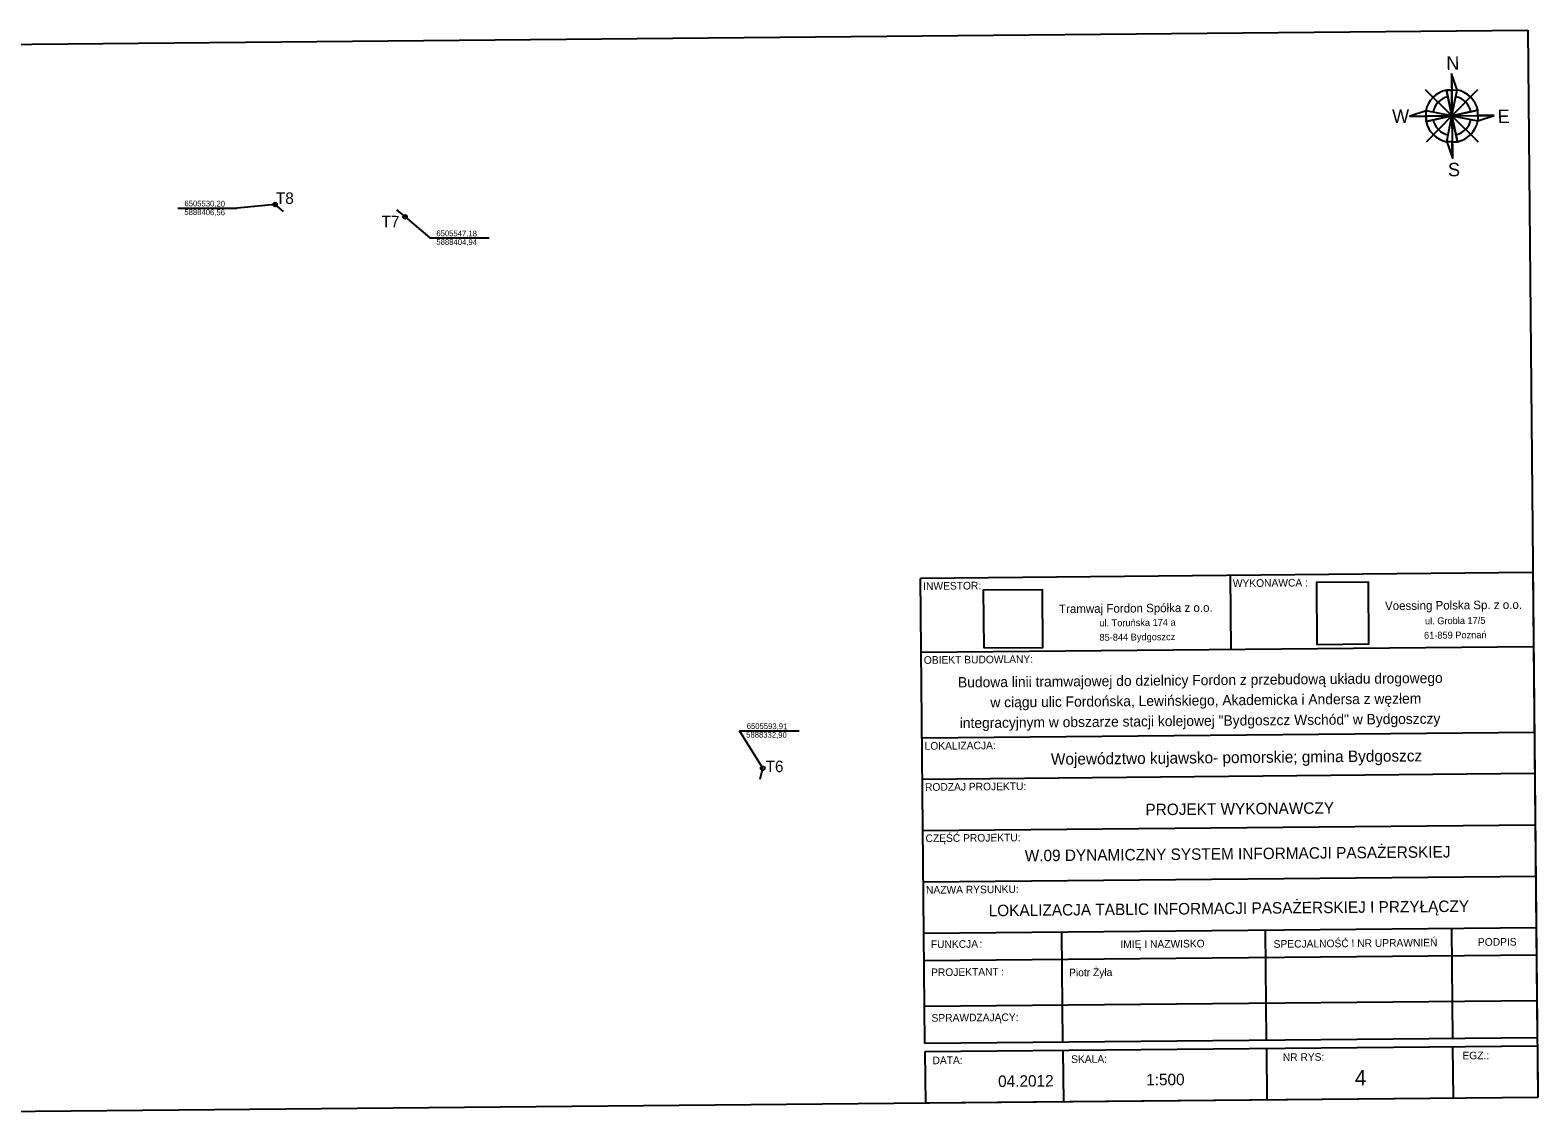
# Model space of a CAD drawing. Extents: x 6505045 to 6511721, y 5887996 to 5893535.
# Drawn here: x 6505498.2 to 6505695.2, y 5888288 to 5888429.3 of the extents above; entities that cross this region are included whole.
import ezdxf

# ---------------------------------------------------------------- set-up
doc = ezdxf.new("R2010")
doc.units = 0
for name, color, linetype in [('__legenda', 7, 'Continuous'), ('Default', 7, 'Continuous'), ('P_2 tablice LCD', 7, 'Continuous'), ('P_lokalizacja slupka', 7, 'Continuous'), ('P_opisy', 7, 'Continuous'), ('P_tabela', 7, 'Continuous'), ('P_wsporzedne', 7, 'Continuous'), ('P_znak północy', 7, 'Continuous'), ('SA_Linie-020', 7, 'Continuous'), ('SA_Stempel_Text-020', 7, 'Continuous'), ('SA_Stempel_Text-030', 7, 'Continuous'), ('SA_Stempel_Text-035', 7, 'Continuous'), ('SA_Unterschrift_Text', 7, 'Continuous')]:
    doc.layers.add(name, color=color, linetype=linetype)

msp = doc.modelspace()

# ---------------------------------------------------------------- linework, layer by layer
at = {"layer": '__legenda'}
msp.add_lwpolyline([(6505666.3, 5888349.09), (6505673.1, 5888349.15), (6505673.03, 5888357.22), (6505666.23, 5888357.16)], close=True, dxfattribs=at)
at = {"layer": 'Default'}
msp.add_lwpolyline([(6505622.78, 5888348.62), (6505630.51, 5888348.69), (6505630.44, 5888356.23), (6505622.71, 5888356.16)], close=True, dxfattribs=at)
at = {"layer": 'P_2 tablice LCD'}
for p, q in [((6505531.32, 5888405.65), (6505530.2, 5888406.56)), ((6505546.05, 5888405.86), (6505547.18, 5888404.94)), ((6505593.58, 5888331.48), (6505593.91, 5888332.9))]:
    msp.add_line(p, q, dxfattribs=at)
at = {"layer": 'P_lokalizacja slupka'}
for centre in [(6505530.2, 5888406.56), (6505547.18, 5888404.94), (6505593.91, 5888332.9)]:
    msp.add_circle(centre, 0.25, dxfattribs=at)
at = {"layer": 'P_tabela'}
for p, q in [((6505492.87, 5888427.46), (6505693.86, 5888429.33)), ((6505492.87, 5888427.46), (6505693.86, 5888429.33)), ((6505492.87, 5888427.46), (6505693.86, 5888429.33)), ((6505693.86, 5888429.33), (6505695.16, 5888289.89)), ((6505693.86, 5888429.33), (6505695.16, 5888289.89)), ((6505693.86, 5888429.33), (6505695.16, 5888289.89)), ((6505695.16, 5888289.89), (6505494.18, 5888288.01)), ((6505695.16, 5888289.89), (6505494.18, 5888288.01)), ((6505695.16, 5888289.89), (6505494.18, 5888288.01))]:
    msp.add_line(p, q, dxfattribs=at)
at = {"layer": 'P_wsporzedne'}
for p, q in [((6505517.5, 5888406.08), (6505525.27, 5888406.08)), ((6505530.2, 5888406.56), (6505525.27, 5888406.08)), ((6505547.18, 5888404.94), (6505550.41, 5888402.18)), ((6505550.41, 5888402.18), (6505558.18, 5888402.18)), ((6505590.88, 5888337.8), (6505598.65, 5888337.8)), ((6505593.91, 5888332.9), (6505590.88, 5888337.8))]:
    msp.add_line(p, q, dxfattribs=at)
at = {"layer": 'P_znak północy'}
for p, q in [((6505683.89, 5888423.66), (6505683.99, 5888412.62)), ((6505683.89, 5888423.66), (6505683.99, 5888412.62)), ((6505683.89, 5888423.66), (6505683.99, 5888412.62)), ((6505683.92, 5888418.14), (6505680.49, 5888421.52)), ((6505683.92, 5888418.14), (6505680.49, 5888421.52)), ((6505683.92, 5888418.14), (6505680.49, 5888421.52)), ((6505683.22, 5888421.51), (6505683.91, 5888421.51)), ((6505683.93, 5888418.14), (6505683.22, 5888421.51)), ((6505683.22, 5888421.51), (6505683.91, 5888421.51)), ((6505683.93, 5888418.14), (6505683.22, 5888421.51)), ((6505683.22, 5888421.51), (6505683.91, 5888421.51)), ((6505683.93, 5888418.14), (6505683.22, 5888421.51)), ((6505683.91, 5888421.51), (6505684.6, 5888421.52)), ((6505683.91, 5888421.51), (6505684.6, 5888421.52)), ((6505683.91, 5888421.51), (6505684.6, 5888421.52)), ((6505683.93, 5888418.14), (6505684.6, 5888421.52)), ((6505683.93, 5888418.14), (6505684.6, 5888421.52)), ((6505683.93, 5888418.14), (6505684.6, 5888421.52)), ((6505683.94, 5888418.15), (6505687.32, 5888421.58)), ((6505683.94, 5888418.15), (6505687.32, 5888421.58)), ((6505683.94, 5888418.15), (6505687.32, 5888421.58)), ((6505678.42, 5888418.08), (6505689.46, 5888418.19)), ((6505678.42, 5888418.08), (6505689.46, 5888418.19)), ((6505678.42, 5888418.08), (6505689.46, 5888418.19)), ((6505683.93, 5888418.14), (6505680.55, 5888418.79)), ((6505683.93, 5888418.14), (6505680.55, 5888418.79)), ((6505683.93, 5888418.14), (6505680.55, 5888418.79)), ((6505683.94, 5888418.15), (6505680.55, 5888414.69)), ((6505683.94, 5888418.15), (6505680.55, 5888414.69)), ((6505683.94, 5888418.15), (6505680.55, 5888414.69)), ((6505680.56, 5888418.1), (6505683.92, 5888418.14)), ((6505680.56, 5888418.1), (6505683.92, 5888418.14)), ((6505680.56, 5888418.1), (6505683.92, 5888418.14)), ((6505680.57, 5888417.41), (6505680.56, 5888418.1)), ((6505680.57, 5888417.41), (6505680.56, 5888418.1)), ((6505680.57, 5888417.41), (6505680.56, 5888418.1)), ((6505680.57, 5888417.41), (6505683.93, 5888418.14)), ((6505683.92, 5888418.14), (6505680.57, 5888417.41)), ((6505680.57, 5888417.41), (6505683.93, 5888418.14)), ((6505683.92, 5888418.14), (6505680.57, 5888417.41)), ((6505680.57, 5888417.41), (6505683.93, 5888418.14)), ((6505683.92, 5888418.14), (6505680.57, 5888417.41)), ((6505683.28, 5888414.75), (6505683.93, 5888418.14)), ((6505683.28, 5888414.75), (6505683.93, 5888418.14)), ((6505683.28, 5888414.75), (6505683.93, 5888418.14)), ((6505683.93, 5888418.14), (6505687.31, 5888418.86)), ((6505683.93, 5888418.14), (6505687.31, 5888418.86)), ((6505683.93, 5888418.14), (6505687.31, 5888418.86)), ((6505683.93, 5888418.14), (6505687.32, 5888417.48)), ((6505683.93, 5888418.14), (6505684.66, 5888414.76)), ((6505683.93, 5888418.14), (6505687.32, 5888417.48)), ((6505683.93, 5888418.14), (6505684.66, 5888414.76)), ((6505683.93, 5888418.14), (6505687.32, 5888417.48)), ((6505683.93, 5888418.14), (6505684.66, 5888414.76)), ((6505683.94, 5888418.15), (6505687.38, 5888414.75)), ((6505683.94, 5888418.15), (6505687.38, 5888414.75)), ((6505683.94, 5888418.15), (6505687.38, 5888414.75))]:
    msp.add_line(p, q, dxfattribs=at)
for points in [[(6505683.89, 5888423.66), (6505683.91, 5888421.51), (6505683.91, 5888421.51), (6505684.6, 5888421.52), (6505683.89, 5888423.66)], [(6505683.89, 5888423.66), (6505683.91, 5888421.51), (6505683.91, 5888421.51), (6505684.6, 5888421.52), (6505683.89, 5888423.66)], [(6505683.89, 5888423.66), (6505683.91, 5888421.51), (6505683.91, 5888421.51), (6505684.6, 5888421.52), (6505683.89, 5888423.66)], [(6505683.94, 5888418.15), (6505683.91, 5888421.51), (6505683.22, 5888421.51), (6505683.93, 5888418.14), (6505683.94, 5888418.15)], [(6505683.94, 5888418.15), (6505683.91, 5888421.51), (6505683.22, 5888421.51), (6505683.93, 5888418.14), (6505683.94, 5888418.15)], [(6505683.94, 5888418.15), (6505683.91, 5888421.51), (6505683.22, 5888421.51), (6505683.93, 5888418.14), (6505683.94, 5888418.15)], [(6505680.56, 5888418.1), (6505680.55, 5888418.79), (6505678.42, 5888418.08), (6505680.56, 5888418.1)], [(6505680.56, 5888418.1), (6505680.55, 5888418.79), (6505678.42, 5888418.08), (6505680.56, 5888418.1)], [(6505680.56, 5888418.1), (6505680.55, 5888418.79), (6505678.42, 5888418.08), (6505680.56, 5888418.1)], [(6505683.92, 5888418.14), (6505680.56, 5888418.1), (6505680.57, 5888417.41), (6505683.92, 5888418.14)], [(6505683.92, 5888418.14), (6505680.56, 5888418.1), (6505680.57, 5888417.41), (6505683.92, 5888418.14)], [(6505683.92, 5888418.14), (6505680.56, 5888418.1), (6505680.57, 5888417.41), (6505683.92, 5888418.14)], [(6505683.94, 5888418.14), (6505683.94, 5888418.14), (6505683.95, 5888418.14), (6505687.32, 5888418.17), (6505687.31, 5888418.86), (6505683.94, 5888418.14)], [(6505683.94, 5888418.14), (6505683.94, 5888418.14), (6505683.95, 5888418.14), (6505687.32, 5888418.17), (6505687.31, 5888418.86), (6505683.94, 5888418.14)], [(6505683.94, 5888418.14), (6505683.94, 5888418.14), (6505683.95, 5888418.14), (6505687.32, 5888418.17), (6505687.31, 5888418.86), (6505683.94, 5888418.14)], [(6505683.97, 5888414.76), (6505684.66, 5888414.76), (6505683.94, 5888418.13), (6505683.97, 5888414.76)], [(6505683.97, 5888414.76), (6505684.66, 5888414.76), (6505683.94, 5888418.13), (6505683.97, 5888414.76)], [(6505683.97, 5888414.76), (6505684.66, 5888414.76), (6505683.94, 5888418.13), (6505683.97, 5888414.76)], [(6505689.46, 5888418.19), (6505687.32, 5888418.17), (6505687.32, 5888417.48), (6505689.46, 5888418.19)], [(6505689.46, 5888418.19), (6505687.32, 5888418.17), (6505687.32, 5888417.48), (6505689.46, 5888418.19)], [(6505689.46, 5888418.19), (6505687.32, 5888418.17), (6505687.32, 5888417.48), (6505689.46, 5888418.19)], [(6505683.97, 5888414.76), (6505683.28, 5888414.75), (6505683.99, 5888412.62), (6505683.97, 5888414.76)], [(6505683.97, 5888414.76), (6505683.28, 5888414.75), (6505683.99, 5888412.62), (6505683.97, 5888414.76)], [(6505683.97, 5888414.76), (6505683.28, 5888414.75), (6505683.99, 5888412.62), (6505683.97, 5888414.76)]]:
    msp.add_lwpolyline(points, dxfattribs=at)
for centre, radius, start, end in [((6505683.93, 5888418.14), 3.45, 102.0474, 168.9738), ((6505683.93, 5888418.14), 3.45, 102.0474, 168.9738), ((6505683.93, 5888418.14), 3.45, 102.0474, 168.9738), ((6505683.94, 5888418.15), 2.53, 102.1671, 169.2958), ((6505683.94, 5888418.15), 2.53, 102.1671, 169.2958), ((6505683.94, 5888418.15), 2.53, 102.1671, 169.2958), ((6505683.94, 5888418.15), 2.53, 11.7816, 78.9353), ((6505683.94, 5888418.15), 2.53, 11.7816, 78.9353), ((6505683.94, 5888418.15), 2.53, 11.7816, 78.9353), ((6505683.94, 5888418.14), 3.45, 12.0554, 79.0163), ((6505683.94, 5888418.14), 3.45, 12.0554, 79.0163), ((6505683.94, 5888418.14), 3.45, 12.0554, 79.0163), ((6505683.93, 5888418.13), 3.45, 192.0538, 259.0158), ((6505683.93, 5888418.13), 3.45, 192.0538, 259.0158), ((6505683.93, 5888418.13), 3.45, 192.0538, 259.0158), ((6505683.94, 5888418.15), 2.53, 192.3917, 259.0318), ((6505683.94, 5888418.15), 2.53, 192.3917, 259.0318), ((6505683.94, 5888418.15), 2.53, 192.3917, 259.0318), ((6505683.94, 5888418.15), 2.53, 282.0081, 348.6723), ((6505683.94, 5888418.15), 2.53, 282.0081, 348.6723), ((6505683.94, 5888418.15), 2.53, 282.0081, 348.6723), ((6505683.94, 5888418.13), 3.45, 282.0538, 349.0163), ((6505683.94, 5888418.13), 3.45, 282.0538, 349.0163), ((6505683.94, 5888418.13), 3.45, 282.0538, 349.0163)]:
    msp.add_arc(centre, radius, start, end, dxfattribs=at)
at = {"layer": 'SA_Linie-020'}
for p, q in [((6505694.52, 5888358.46), (6505614.52, 5888357.71)), ((6505614.96, 5888311.29), (6505614.52, 5888357.71)), ((6505654.97, 5888358.09), (6505655.06, 5888348.43)), ((6505694.52, 5888358.46), (6505695.09, 5888297.67)), ((6505614.61, 5888348.05), (6505694.61, 5888348.8)), ((6505694.72, 5888337.57), (6505614.72, 5888336.83)), ((6505694.77, 5888332.2), (6505614.77, 5888331.45)), ((6505694.83, 5888325.48), (6505614.83, 5888324.73)), ((6505694.83, 5888325.48), (6505614.83, 5888324.73)), ((6505694.89, 5888318.76), (6505614.89, 5888318.01)), ((6505694.95, 5888312.04), (6505614.96, 5888311.29)), ((6505633.11, 5888297.09), (6505632.98, 5888311.46)), ((6505659.55, 5888311.71), (6505659.69, 5888297.34)), ((6505683.89, 5888311.94), (6505684.02, 5888297.56)), ((6505615.09, 5888296.92), (6505614.96, 5888311.29)), ((6505694.99, 5888308.48), (6505614.99, 5888307.73)), ((6505695.04, 5888302.52), (6505615.05, 5888301.77)), ((6505695.09, 5888297.67), (6505615.09, 5888296.92)), ((6505695.1, 5888296.61), (6505615.1, 5888295.86)), ((6505615.1, 5888295.86), (6505615.16, 5888289.14)), ((6505633.12, 5888296.03), (6505633.18, 5888289.31)), ((6505659.7, 5888296.28), (6505659.76, 5888289.56)), ((6505684.03, 5888296.5), (6505684.1, 5888289.78)), ((6505695.1, 5888296.61), (6505695.16, 5888289.89)), ((6505695.16, 5888289.89), (6505615.16, 5888289.14))]:
    msp.add_line(p, q, dxfattribs=at)

# ---------------------------------------------------------------- texts
at = {"layer": 'P_opisy'}
for s, p in [('T8', (6505530.3, 5888406.64)), ('T7', (6505544.1, 5888403.58)), ('T6', (6505594.28, 5888332.4))]:
    msp.add_text(s, height=1.501, rotation=359.8095, dxfattribs=at).set_placement(p)
at = {"layer": 'P_wsporzedne'}
for s, p in [('5888406,56', (6505518.35, 5888405.19)), ('6505530,20', (6505518.36, 5888406.32)), ('5888404,94', (6505551.27, 5888401.29)), ('6505547,18', (6505551.27, 5888402.42)), ('5888332,90', (6505591.74, 5888336.91)), ('6505593,91', (6505591.81, 5888338.04))]:
    msp.add_text(s, height=0.751, rotation=359.6048, dxfattribs=at).set_placement(p)
at = {"layer": 'P_znak północy'}
for s, p in [('N', (6505683.21, 5888424.14)), ('N', (6505683.21, 5888424.14)), ('N', (6505683.21, 5888424.14)), ('W', (6505676.14, 5888417.21)), ('W', (6505676.14, 5888417.21)), ('W', (6505676.14, 5888417.21)), ('E', (6505689.92, 5888417.19)), ('E', (6505689.92, 5888417.19)), ('E', (6505689.92, 5888417.19)), ('S', (6505683.43, 5888410.23)), ('S', (6505683.43, 5888410.23)), ('S', (6505683.43, 5888410.23))]:
    msp.add_text(s, height=1.76, rotation=0.535, dxfattribs=at).set_placement(p)
at = {"layer": 'SA_Stempel_Text-020'}
for s, p in [('INWESTOR:', (6505614.87, 5888356.2)), ('WYKONAWCA :', (6505655.32, 5888356.57)), ('OBIEKT BUDOWLANY:', (6505614.96, 5888346.54)), ('LOKALIZACJA:', (6505615.06, 5888335.31)), ('RODZAJ PROJEKTU:', (6505615.11, 5888329.94)), ('CZĘŚĆ PROJEKTU:', (6505615.18, 5888323.25)), ('NAZWA RYSUNKU:', (6505615.24, 5888316.5)), ('FUNKCJA', (6505615.87, 5888309.4)), (':', (6505622.2, 5888309.46)), ('IMIĘ I NAZWISKO', (6505640.64, 5888309.4)), ('SPECJALNOŚĆ I NR UPRAWNIEŃ', (6505660.65, 5888309.44)), ('PODPIS', (6505687.34, 5888309.69)), ('PROJEKTANT', (6505615.9, 5888305.74)), (':', (6505625.04, 5888305.83)), ('SPRAWDZAJĄCY:', (6505615.96, 5888299.78)), ('NR RYS:', (6505661.85, 5888294.64)), ('EGZ.:', (6505685.31, 5888294.86)), ('DATA:', (6505616.09, 5888294.23)), ('SKALA:', (6505634.2, 5888294.39))]:
    msp.add_text(s, height=1, rotation=0.535, dxfattribs=at).set_placement(p)
at = {"layer": 'SA_Stempel_Text-030'}
for s, height, p in [('04.2012', 1.5, (6505624.66, 5888291.26)), ('1:500', 1.5, (6505644, 5888291.46)), ('4', 2, (6505671.26, 5888291.46))]:
    msp.add_text(s, height=height, rotation=0.535, dxfattribs=at).set_placement(p)
at = {"layer": 'SA_Stempel_Text-035'}
for s, height, p in [('Budowa linii tramwajowej do dzielnicy Fordon z przebudową układu drogowego', 1.35, (6505619.42, 5888343.45)), ('w ciągu ulic Fordońska, Lewińskiego, Akademicka i Andersa z węzłem', 1.35, (6505623.65, 5888340.84)), ('integracyjnym w obszarze stacji kolejowej "Bydgoszcz Wschód" w Bydgoszczy', 1.35, (6505619.65, 5888338.14)), ('Województwo kujawsko- pomorskie; gmina Bydgoszcz', 1.5, (6505631.56, 5888333.35)), ('PROJEKT WYKONAWCZY', 1.5, (6505643.91, 5888326.75)), ('W.09 DYNAMICZNY SYSTEM INFORMACJI PASAŻERSKIEJ', 1.5, (6505628.14, 5888320.73)), ('LOKALIZACJA TABLIC INFORMACJI PASAŻERSKIEJ I PRZYŁĄCZY', 1.5, (6505623.43, 5888313.56))]:
    msp.add_text(s, height=height, rotation=0.535, dxfattribs=at).set_placement(p)
at = {"layer": 'SA_Unterschrift_Text'}
for s, height, p in [('Voessing Polska Sp. z o.o.', 1.125, (6505675.2, 5888353.56)), ('Tramwaj Fordon Spółka z o.o.', 1.125, (6505632.62, 5888353.16)), ('ul. Grobla 17/5', 0.9, (6505680.42, 5888351.7)), ('ul. Toruńska 174 a', 0.9, (6505637.88, 5888351.43)), ('61-859 Poznań', 0.9, (6505680.3, 5888349.82)), ('85-844 Bydgoszcz', 0.9, (6505637.9, 5888349.55)), ('Piotr Żyła', 1, (6505633.93, 5888305.71))]:
    msp.add_text(s, height=height, rotation=0.535, dxfattribs=at).set_placement(p)

doc.saveas('drawing.dxf')
